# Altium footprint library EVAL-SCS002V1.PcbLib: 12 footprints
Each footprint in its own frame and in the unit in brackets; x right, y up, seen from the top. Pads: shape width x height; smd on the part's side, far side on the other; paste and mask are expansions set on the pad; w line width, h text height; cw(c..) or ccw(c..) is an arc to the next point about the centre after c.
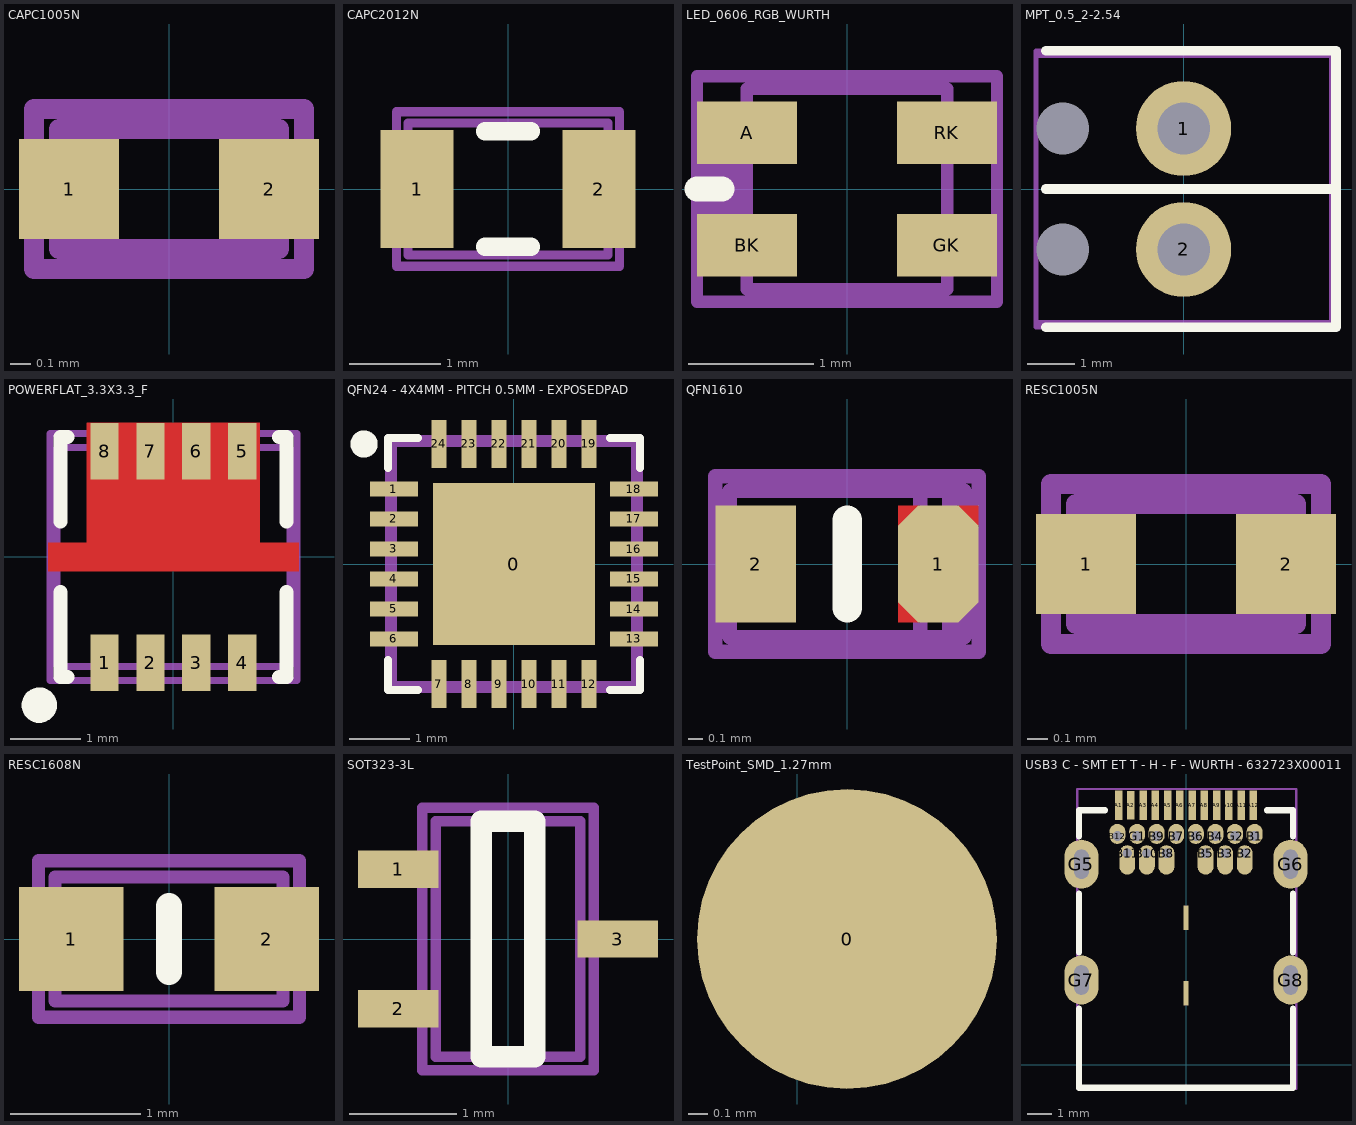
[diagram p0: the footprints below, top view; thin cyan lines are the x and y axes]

## CAPC1005N [mm] "Chip Capacitor, Body 1.0x0.5mm, IPC Medium Density"
height 0.6
pads (2):
  rect 0.5x0.5 smd: 1(-0.5,0) 2(0.5,0)
Mechanical 13:
  lines w0.1: -0.55,-0.3 -0.55,0.3 0.55,0.3 0.55,-0.3 -0.55,-0.3
Mechanical 15:
  lines w0.1: -0.675,-0.4 -0.675,0.4 0.675,0.4 0.675,-0.4 -0.675,-0.4
  text ".designator" at 0.508,0.127 h0.3
3D body "CAPC1005X55N.step": height 0.55, standoff 0, extent -0.525,-0.275 0.525,0.275

## CAPC2012N [mm] "Chip Capacitor, Body 2.0x1.3mm, IPC Medium Density"
height 1.25
pads (2):
  rect 0.8x1.3 smd: 1(-1,0) 2(1,0)
Top Overlay:
  lines w0.2: -0.254,-0.635 0.254,-0.635 ; -0.254,0.635 0.254,0.635
Mechanical 13:
  lines w0.1: -1.1,-0.725 -1.1,0.725 1.1,0.725 1.1,-0.725 -1.1,-0.725
Mechanical 15:
  lines w0.1: -1.225,-0.85 -1.225,0.85 1.225,0.85 1.225,-0.85 -1.225,-0.85
  text ".designator" at -1,-0.25 h0.5
3D body "CAPC2012X135N.step": height 1.35, standoff 0, extent -1.1,-0.725 1.1,0.725

## LED_0606_RGB_WURTH [mm] "Chip; Body 1.6 x 1.6 mm (LxW typ) WURTH"
height 0.55
pads (4):
  rect 0.8x0.5 smd: A(-0.8,0.45) BK(-0.8,-0.45) GK(0.8,-0.45) RK(0.8,0.45)
Top Overlay:
  lines w0.2: -1.2,0 -1,0
Mechanical 13:
  lines w0.1: -0.8,-0.8 -0.8,0.8 0.8,0.8 0.8,-0.8 -0.8,-0.8
Mechanical 15:
  lines w0.1: -1.2,-0.2 -0.9,-0.2 -0.9,0.2 -1.2,0.2 ; -1.1,-0.2 -1.1,0.2 ; -1,-0.2 -1,0.2 ; 1.2,-0.6 1.2,0 ; -1.2,-0.9 1.2,-0.9 1.2,0.9 -1.2,0.9 -1.2,-0.9
  text ".designator" at 1.016,0.254 h0.5
3D body "STEP-WL-SFCW-0606-rev1.stp": height 0.4, standoff 0, extent -0.8,-0.8 0.8,0.8

## MPT_0.5_2-2.54 [mm] "Screw  PCB terminal block, 2 positions 2.54mm pitch"
height 8.5
pads (4):
  round 0 hole 1.1: 01(-2.54,1.27) 02(-2.54,-1.27)
  round 2 hole 1.1: 1(0,1.27) 2(0,-1.27)
Top Overlay:
  lines w0.2: -2.9,-2.9 3.2,-2.9 3.2,2.9 -2.9,2.9 ; -2.9,0 3.2,0
Mechanical 3:
  text "outside" at -3.556,-1.524 h0.5
Mechanical 13:
  lines w0.1: -3.1,-2.8 3.1,-2.8 3.1,2.78 ; -3.1,-2.78 -3.1,2.8 3.1,2.8
Mechanical 15:
  lines w0.1: -3.1,-2.9 -3.1,2.9 3.2,2.9 3.2,-2.9 -3.1,-2.9
  text ".designator" at 1.524,0.508 h1
3D body "13996.stp": height 8.5, standoff -3.5, extent -3.1,-2.77 3.1,2.77

## POWERFLAT_3.3X3.3_F [mm] "PowerFLAT™ 3.3 x 3.3 type F"
height 1
pads (8):
  rect 0.4x0.8 smd: 1(-0.975,-1.5) 2(-0.325,-1.5) 3(0.325,-1.5) 4(0.975,-1.5) 5(0.975,1.5) 6(0.325,1.5) 7(-0.325,1.5) 8(-0.975,1.5)
Top Layer:
  region: 0,1.9 1.225,1.9 1.225,0.2 1.775,0.2 1.775,-0.2 0,-0.2
  region: 0,1.9 -1.225,1.9 -1.225,0.2 -1.775,0.2 -1.775,-0.2 0,-0.2
Top Overlay:
  circle w0.25: c-1.9,-2.1 r0.125
  lines w0.2: -1.6,-0.5 -1.6,-1.7 -1.5,-1.7 ; -1.6,0.5 -1.6,1.7 -1.5,1.7 ; 1.5,-1.7 1.6,-1.7 1.6,-0.5 ; 1.5,1.7 1.6,1.7 1.6,0.5
Top Paste:
  region: 0,1.9 -1.225,1.9 -1.225,0.2 -1.8,0.2 -1.8,-0.2 0,-0.2
  region: 0,1.9 1.225,1.9 1.225,0.2 1.8,0.2 1.8,-0.2 0,-0.2
Top Solder:
  region: 0,2.025 1.35,2.025 1.35,0.325 1.9,0.325 1.9,-0.325 0,-0.325
  region: 0,2.025 -1.35,2.025 -1.35,0.325 -1.9,0.325 -1.9,-0.325 0,-0.325
Mechanical 13:
  lines w0.1: -1.65,-1.55 1.65,-1.55 1.65,1.55 -1.65,1.55 -1.65,-1.55
Mechanical 15:
  lines w0.1: -1.75,-1.75 1.75,-1.75 1.75,1.75 -1.75,1.75 -1.75,-1.75
  text ".designator" at 0.25,-0.9 h0.5
3D body "User Library-DFN8_3x3_0_65Pitch.STEP": height 0.8, standoff 0, extent -1.55,-1.6 1.55,1.6

## QFN24 - 4X4MM - PITCH 0.5MM - EXPOSEDPAD [mm] "QFN24 - 4X4mm - pitch 0.5mm - ExposedPAD"
height 2.794
pads (25):
  rect 2.7x2.7 smd: 0(0,0)
  rect 0.8x0.25 smd: 1(-2,1.25) 2(-2,0.75) 3(-2,0.25) 4(-2,-0.25) 5(-2,-0.75) 6(-2,-1.25) 13(2,-1.25) 14(2,-0.75) 15(2,-0.25) 16(2,0.25) 17(2,0.75) 18(2,1.25)
  rect 0.25x0.8 smd: 7(-1.25,-2) 8(-0.75,-2) 9(-0.25,-2) 10(0.25,-2) 11(0.75,-2) 12(1.25,-2) 19(1.25,2) 20(0.75,2) 21(0.25,2) 22(-0.25,2) 23(-0.75,2) 24(-1.25,2)
Top Overlay:
  circle w0.254: c-2.5,2 r0.1
  lines w0.127: -2.1,-1.6 -2.1,-2.1 -1.6,-2.1 ; -2.1,1.6 -2.1,2.1 -1.6,2.1 ; 1.6,-2.1 2.1,-2.1 2.1,-1.6 ; 1.6,2.1 2.1,2.1 2.1,1.6
Mechanical 13:
  lines w0.1: -2,-2 2,-2 2,2 -2,2 -2,-2
Mechanical 15:
  lines w0.1: -2.1,-2.1 2.1,-2.1 2.1,2.1 -2.1,2.1 -2.1,-2.1
  text ".designator" at -0.8,-0.25 h0.5
3D body "User Library-QFN24-4x4-0_5.STEP": height 1, standoff 0, extent -2,-2 2,2

## QFN1610 [mm] "QFN 1610"
height 0.6
pads (2):
  oct 0.55x0.8 smd paste+0 mask+0.1: 1(0.625,0)
  rect 0.55x0.8 smd: 2(-0.625,0)
Top Layer:
  rectangle: 0.35,0.25 0.5,0.4
  region: 0.5,-0.4 0.5,-0.25 0.35,-0.25 0.35,-0.4
  region: 0.75,0.4 0.75,0.25 0.9,0.25 0.9,0.4
Top Overlay:
  lines w0.2: 0.002,-0.3 0.002,0.3
Top Paste:
  rectangle: 0.35,0.25 0.5,0.4
  rectangle: 0.35,-0.4 0.5,-0.25
  rectangle: 0.75,0.25 0.9,0.4
Top Solder:
  rectangle: 0.25,0.3 0.475,0.5
  rectangle: 0.8,0.276 1,0.501
  rectangle: 0.25,-0.5 0.475,-0.275
Mechanical 13:
  lines w0.1: -0.8,-0.5 0.8,-0.5 0.8,0.5 -0.8,0.5 -0.8,-0.5
Mechanical 15:
  lines w0.1: 0.5,-0.6 0.5,0.6 ; 0.7,-0.6 0.7,0.6 ; -0.9,-0.6 0.9,-0.6 0.9,0.6 -0.9,0.6 -0.9,-0.6
  text ".designator" at -0.8,-0.25 h0.5
3D body: height 0.55, standoff 0.05, extent -0.8,-0.5 0.8,0.5

## RESC1005N [mm] "Chip Resistor, Body 1.0x0.5mm, IPC Medium Density"
height 0.45
pads (2):
  rect 0.5x0.5 smd: 1(-0.5,0) 2(0.5,0)
Mechanical 13:
  lines w0.1: -0.55,-0.3 0.55,-0.3 0.55,0.3 -0.55,0.3 -0.55,-0.3
Mechanical 15:
  lines w0.1: -0.675,-0.4 0.675,-0.4 0.675,0.4 -0.675,0.4 -0.675,-0.4
  text ".designator" at 0.508,0.127 h0.3
3D body "User Library-0402.STEP": height 0.35, standoff 0, extent -0.5,-0.25 0.5,0.25

## RESC1608N [mm] "Chip Resistor, Body 1.6x0.8mm, IPC Medium Density"
height 0.6
pads (2):
  rect 0.8x0.8 smd: 1(-0.75,0) 2(0.75,0)
Top Overlay:
  lines w0.2: 0,-0.254 0,0.254
Mechanical 13:
  lines w0.1: -0.875,-0.475 0.875,-0.475 0.875,0.475 -0.875,0.475 -0.875,-0.475
Mechanical 15:
  lines w0.1: -1,-0.6 1,-0.6 1,0.6 -1,0.6 -1,-0.6
  text ".designator" at 0.889,0.254 h0.5
3D body "RESC1608X55N.step": height 0.55, standoff 0, extent -0.875,-0.475 0.875,0.475

## SOT323-3L [mm] "SOT323, 3-Leads, Body 2.2x2.4mm (max), Pitch 0.65mm, IPC Medium Density"
height 1.8
pads (3):
  rect 0.75x0.35 smd: 1(-1.025,0.65) 2(-1.025,-0.65) 3(1.025,0)
Top Overlay:
  lines w0.2: -0.25,-1.1 -0.25,1.1 0.25,1.1 0.25,-1.1 -0.25,-1.1
Mechanical 13:
  lines w0.1: -0.675,-1.1 0.675,-1.1 0.675,1.1 -0.675,1.1 -0.675,-1.1
Mechanical 15:
  lines w0.1: -0.8,-1.225 0.8,-1.225 0.8,1.225 -0.8,1.225 -0.8,-1.225
  text ".designator" at 0.254,-1.016 h0.5
3D body "User Library-sc70-3.STEP": height 1, standoff 0, extent -1.15,-1.05 1.15,1.05

## TestPoint_SMD_1.27mm [mil] "TestPoint_SMD_1.27mm"
pads (1):
  round 60 smd paste-39.37 mask-5: 0(10,190)

## USB3 C - SMT ET T - H - F - WURTH - 632723X00011 [mm] "USB3 type C - montage sur CI - Femmelle - Angle droit - Composant Certifié (x=1 -> PCB height= 1mm TID : 5,200,000,115 // x=3 -> PCB height= 1mm TID : 5,200,000,116)"
height 2.972
pads (32):
  rect 0.3x1.2 smd mask+0: A1(-2.75,10.58) A3(-1.75,10.58) A4(-1.25,10.58) A5(-0.75,10.58) A8(0.75,10.58) A9(1.25,10.58) A10(1.75,10.58) A11(2.25,10.58) A12(2.75,10.58)
  rect 0.3x1.168 smd mask+0: A2(-2.25,10.58)
  rect 0.3x1.199 smd mask+0: A6(-0.25,10.58) A7(0.25,10.58)
  oval 0.65x0.825 hole 0.4 copper offset 0,0.088 mask+0: B1(2.8,9.33) B4(1.2,9.33) B6(0.4,9.33) B7(-0.4,9.33) B9(-1.2,9.33) B12(-2.8,9.33) G1(-2,9.33) G2(2,9.33)
  oval 0.65x1.2 hole 0.4 copper offset 0,-0.275 mask+0: B2(2.4,8.63) B3(1.6,8.63) B5(0.8,8.63) B8(-0.8,8.63) B10(-1.6,8.63) B11(-2.4,8.63)
  rect 0.2x1 smd: G3(0,6) G4(0,2.9)
  oval 1.4x2 hole 0.6 slot 1.2 at 90 deg: G5(-4.27,8.18) G6(4.27,8.18) G7(-4.27,3.45) G8(4.27,3.45)
Top Overlay:
  lines w0.254: -4.37,2.286 -4.37,-0.95 4.37,-0.95 4.37,2.286 ; -4.37,4.572 -4.37,6.985 ; -4.37,9.323 -4.37,10.38 -3.302,10.38 ; 3.302,10.38 4.37,10.38 4.37,9.323 ; 4.37,4.572 4.37,6.985
Mechanical 15:
  lines w0.1: -4.445,-1 4.5,-1 4.5,11.25 -4.445,11.25 -4.445,-1
  text ".designator" at 0.48,6.731 h1
3D body "Conn-USB_C-Recept-H-Wurth_632723x00011.stp": height 2.97, standoff -1.89, extent -4.37,-0.95 4.37,10.844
